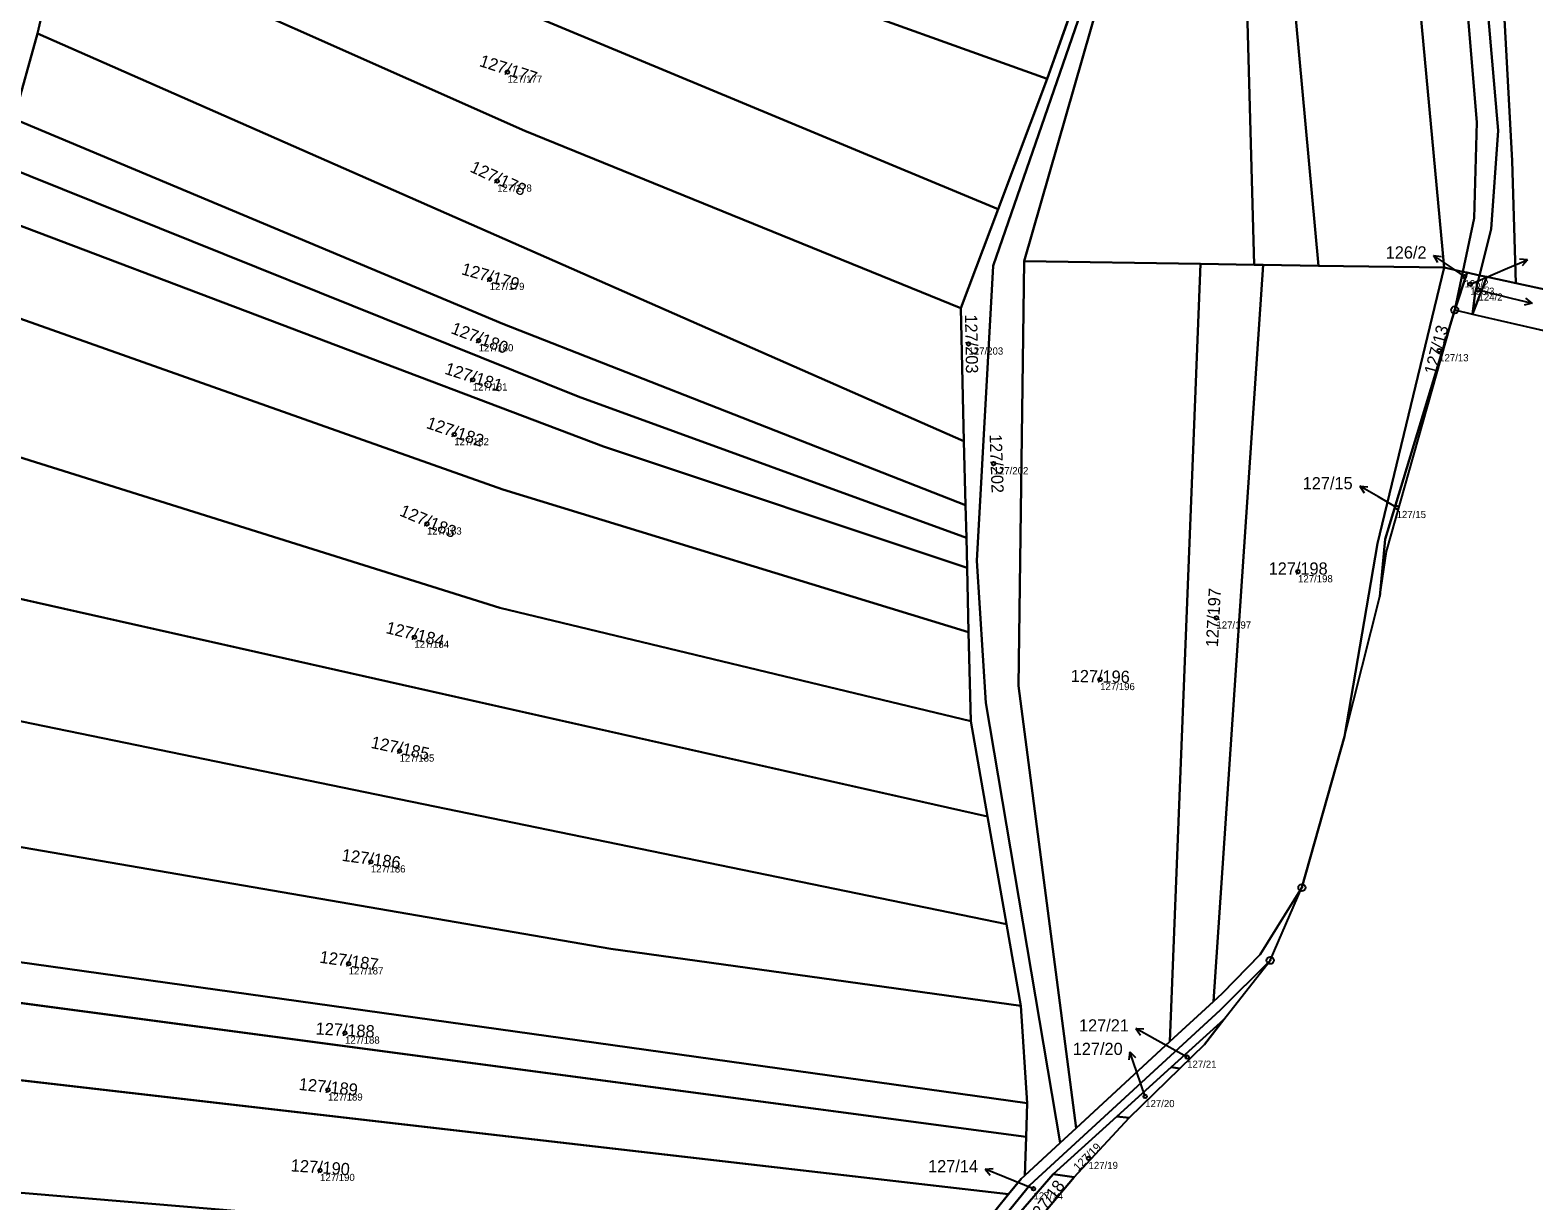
# Model space of a CAD drawing. Extents: x -603967 to -594699, y -1179315 to -1165625.
# Drawn here: x -597543.8 to -597334.3, y -1173385.4 to -1173222.3 of the extents above; entities that cross this region are included whole.
import ezdxf

# ---------------------------------------------------------------- set-up
doc = ezdxf.new("R2010")
doc.units = 0
for name, color, linetype in [('Definiční body', 7, 'Continuous'), ('Hranice parcel', 7, 'Continuous'), ('Parcelní čísla', 7, 'Continuous'), ('Polygon ku', 7, 'Continuous'), ('Polygon parcely', 7, 'Continuous'), ('Pop  PČ popisy', 7, 'Continuous'), ('Značky bodu BP', 7, 'Continuous')]:
    doc.layers.add(name, color=color, linetype=linetype)

msp = doc.modelspace()

# ---------------------------------------------------------------- linework, layer by layer
at = {"layer": 'Definiční body'}
for centre in [(-597477.29, -1173228.12994), (-597478.73, -1173243.29994), (-597343.99, -1173256.61994), (-597479.76, -1173256.98994), (-597343.17, -1173257.65994), (-597342.03, -1173258.45994), (-597481.3, -1173265.53994), (-597413.07, -1173265.98994), (-597347.51, -1173266.91994), (-597482.12, -1173270.98994), (-597484.7, -1173278.60994), (-597409.57, -1173282.65994), (-597353.44, -1173288.75994), (-597488.5, -1173291.05994), (-597367.17, -1173297.69994), (-597378.54, -1173304.14994), (-597490.25, -1173306.82994), (-597394.74, -1173312.71994), (-597492.31, -1173322.67994), (-597496.32, -1173338.11994), (-597499.41, -1173352.31994), (-597499.92, -1173361.95994), (-597382.62, -1173365.31994), (-597502.29, -1173369.88994), (-597388.46, -1173370.79994), (-597396.35, -1173379.41994), (-597503.39, -1173381.08994), (-597404.02, -1173383.65994)]:
    msp.add_circle(centre, 0.25, dxfattribs=at)
at = {"layer": 'Hranice parcel'}
for p, q in [((-597539.27, -1173207.67), (-597542.73, -1173222.74)), ((-597402.11, -1173229.07), (-597397.53, -1173216.17)), ((-597542.73, -1173222.74), (-597546.06, -1173234.64)), ((-597542.73, -1173222.74), (-597413.7, -1173279.52)), ((-597408.96, -1173247.24), (-597402.11, -1173229.07)), ((-597414.15, -1173260.99), (-597408.96, -1173247.24)), ((-597380.77, -1173254.84), (-597405.32, -1173254.45)), ((-597385.02, -1173363.15), (-597380.77, -1173254.84)), ((-597373.26, -1173254.96), (-597380.77, -1173254.84)), ((-597378.97, -1173357.58), (-597372.02, -1173254.98)), ((-597372.02, -1173254.98), (-597373.26, -1173254.96)), ((-597364.3, -1173255.1), (-597372.02, -1173254.98)), ((-597346.84, -1173255.37), (-597364.3, -1173255.1)), ((-597344.24, -1173255.93), (-597346.84, -1173255.37)), ((-597344.24, -1173255.93), (-597345.35, -1173261.25)), ((-597345.35, -1173261.25), (-597343.63, -1173256.06)), ((-597344.24, -1173255.93), (-597343.63, -1173256.06)), ((-597343.63, -1173256.06), (-597341.88, -1173256.44)), ((-597340.86, -1173256.64), (-597341.88, -1173256.44)), ((-597342.88, -1173261.85), (-597340.86, -1173256.64)), ((-597336.82, -1173257.52), (-597340.86, -1173256.64)), ((-597413.7, -1173279.52), (-597414.15, -1173260.99)), ((-597354.85, -1173294.92), (-597345.35, -1173261.25)), ((-597345.35, -1173261.25), (-597342.88, -1173261.85)), ((-597342.88, -1173261.85), (-597207.7, -1173292.76)), ((-597413.48, -1173288.43), (-597413.7, -1173279.52)), ((-597413.37, -1173293.01), (-597413.48, -1173288.43)), ((-597413.27, -1173297.18), (-597413.37, -1173293.01)), ((-597355.78, -1173301.19), (-597354.85, -1173294.92)), ((-597567.88, -1173296.4), (-597410.41, -1173331.83)), ((-597413.05, -1173306.13), (-597413.27, -1173297.18)), ((-597360.7, -1173320.68), (-597355.78, -1173301.19)), ((-597412.75, -1173318.55), (-597413.05, -1173306.13)), ((-597573.63, -1173312.68), (-597407.77, -1173346.82)), ((-597410.41, -1173331.83), (-597412.75, -1173318.55)), ((-597360.7, -1173320.68), (-597366.63, -1173341.72)), ((-597407.77, -1173346.82), (-597410.41, -1173331.83)), ((-597371.05, -1173351.85), (-597366.63, -1173341.72)), ((-597584.72, -1173346.58), (-597404.9, -1173371.72)), ((-597405.77, -1173358.17), (-597407.77, -1173346.82)), ((-597588.05, -1173352.06), (-597405.06, -1173376.43)), ((-597377.5, -1173360.1), (-597371.05, -1173351.85)), ((-597404.9, -1173371.72), (-597405.77, -1173358.17)), ((-597378.97, -1173357.58), (-597385.02, -1173363.15)), ((-597384.85, -1173366.74), (-597377.5, -1173360.1)), ((-597594.6, -1173362.84), (-597407.48, -1173384.43)), ((-597385.02, -1173363.15), (-597398.08, -1173375.21)), ((-597392.4, -1173373.59), (-597384.85, -1173366.74)), ((-597390.69, -1173373.8), (-597383.65, -1173366.92)), ((-597383.65, -1173366.92), (-597384.85, -1173366.74)), ((-597405.06, -1173376.43), (-597404.9, -1173371.72)), ((-597401.29, -1173381.61), (-597392.4, -1173373.59)), ((-597390.69, -1173373.8), (-597392.4, -1173373.59)), ((-597398.08, -1173375.21), (-597400.29, -1173377.25)), ((-597398.37, -1173382.03), (-597390.69, -1173373.8)), ((-597405.24, -1173381.82), (-597405.06, -1173376.43)), ((-597400.29, -1173377.25), (-597405.24, -1173381.82)), ((-597608.97, -1173378.82), (-597416.1, -1173395.08)), ((-597407.87, -1173389.24), (-597401.29, -1173381.61)), ((-597398.37, -1173382.03), (-597404.78, -1173389.65)), ((-597401.29, -1173381.61), (-597398.37, -1173382.03)), ((-597407.48, -1173384.43), (-597416.1, -1173395.08))]:
    msp.add_line(p, q, dxfattribs=at)
for points in [[(-597341.88, -1173256.44), (-597340.26, -1173250.03), (-597339.32, -1173236.26), (-597344.17, -1173179.9), (-597353.54, -1173132.63), (-597361.17, -1173091.31), (-597366.08, -1173066.31), (-597374.64, -1173050.36), (-597380.37, -1173039.62), (-597387.47, -1173019.8), (-597399.32, -1172964.53), (-597404.92, -1172923.92), (-597423.04, -1172835.13), (-597437.05, -1172782.74)], [(-597385.23, -1173035.74), (-597369.64, -1173064.26), (-597366.45, -1173075.97), (-597356.05, -1173133.92), (-597346.95, -1173178.93), (-597342.27, -1173235.11), (-597342.62, -1173248.49), (-597344.24, -1173255.93)], [(-597373.26, -1173254.96), (-597374.47, -1173211.02), (-597373.85, -1173166.41), (-597375.69, -1173097.31), (-597378.77, -1173058.37)], [(-597364.3, -1173255.1), (-597367.48, -1173220.7), (-597367.67, -1173176.36), (-597372.2, -1173099.16), (-597376.39, -1173065.79)], [(-597346.84, -1173255.37), (-597353.46, -1173183.74), (-597366.22, -1173097.48), (-597376.39, -1173065.79)], [(-597380.95, -1173103.54), (-597382.69, -1173103.69), (-597389.48, -1173147.51), (-597392.36, -1173174.23), (-597394.01, -1173209.84), (-597409.64, -1173255.1), (-597411.9, -1173296.2), (-597410.66, -1173315.96), (-597400.29, -1173377.25)], [(-597380.95, -1173103.54), (-597388.45, -1173157.59), (-597392.56, -1173210), (-597405.32, -1173254.45)], [(-597531.27, -1173180.19), (-597472.58, -1173203.79), (-597402.11, -1173229.07)], [(-597340.37, -1173184.71), (-597337.35, -1173240.49), (-597336.82, -1173257.52)], [(-597535.59, -1173193.78), (-597474.9, -1173219.8), (-597408.96, -1173247.24)], [(-597539.27, -1173207.67), (-597474.86, -1173236.29), (-597414.15, -1173260.99)], [(-597546.06, -1173234.64), (-597477.92, -1173263.21), (-597413.48, -1173288.43)], [(-597548.33, -1173240.82), (-597467.43, -1173273.3), (-597413.37, -1173293.01)], [(-597550.79, -1173247.41), (-597463.93, -1173280.29), (-597413.27, -1173297.18)], [(-597405.32, -1173254.45), (-597406.11, -1173313.63), (-597398.08, -1173375.21)], [(-597346.84, -1173255.37), (-597356.1, -1173293.81), (-597360.7, -1173320.68)], [(-597341.88, -1173256.44), (-597342.48, -1173258.83), (-597342.88, -1173261.85)], [(-597203.06, -1173285.97), (-597235.54, -1173279.29), (-597273.37, -1173276.16), (-597302.53, -1173264.95), (-597336.82, -1173257.52)], [(-597555.73, -1173258.73), (-597477.92, -1173286.26), (-597413.05, -1173306.13)], [(-597355.78, -1173301.19), (-597355.05, -1173293.18), (-597345.35, -1173261.25)], [(-597559.64, -1173277.25), (-597478.33, -1173302.73), (-597412.75, -1173318.55)], [(-597579.78, -1173330.11), (-597462.89, -1173350.25), (-597405.77, -1173358.17)], [(-597366.63, -1173341.72), (-597372.44, -1173351.02), (-597377.75, -1173356.45), (-597378.97, -1173357.58)], [(-597422.2, -1173415.24), (-597419.31, -1173405.08), (-597414.89, -1173395.86), (-597404.55, -1173383.14), (-597378.04, -1173358.78), (-597371.05, -1173351.85)], [(-597377.5, -1173360.1), (-597380.18, -1173363.56), (-597383.65, -1173366.92)], [(-597405.24, -1173381.82), (-597405.74, -1173382.28), (-597407.48, -1173384.43)]]:
    msp.add_lwpolyline(points, dxfattribs=at)
at = {"layer": 'Polygon ku'}
msp.add_lwpolyline([(-597404.78, -1173389.65), (-597398.37, -1173382.03), (-597390.69, -1173373.8), (-597383.65, -1173366.92), (-597380.18, -1173363.56), (-597377.5, -1173360.1), (-597371.05, -1173351.85), (-597366.63, -1173341.72), (-597360.7, -1173320.68), (-597355.78, -1173301.19), (-597354.85, -1173294.92), (-597345.35, -1173261.25), (-597342.88, -1173261.85), (-597207.7, -1173292.76)], dxfattribs=at)
at = {"layer": 'Polygon parcely'}
for points in [[(-597401.86, -1172966.79), (-597391.47, -1173016.9), (-597386.2, -1173032.57), (-597385.23, -1173035.74), (-597369.64, -1173064.26), (-597366.45, -1173075.97), (-597356.05, -1173133.92), (-597346.95, -1173178.93), (-597342.27, -1173235.11), (-597342.62, -1173248.49), (-597344.24, -1173255.93), (-597343.63, -1173256.06), (-597341.88, -1173256.44), (-597340.26, -1173250.03), (-597339.32, -1173236.26), (-597344.17, -1173179.9), (-597353.54, -1173132.63), (-597361.17, -1173091.31), (-597366.08, -1173066.31), (-597374.64, -1173050.36), (-597380.37, -1173039.62), (-597387.47, -1173019.8), (-597399.32, -1172964.53)], [(-597399.32, -1172964.53), (-597387.47, -1173019.8), (-597380.37, -1173039.62), (-597374.64, -1173050.36), (-597366.08, -1173066.31), (-597361.17, -1173091.31), (-597353.54, -1173132.63), (-597344.17, -1173179.9), (-597339.32, -1173236.26), (-597340.26, -1173250.03), (-597341.88, -1173256.44), (-597340.86, -1173256.64), (-597336.82, -1173257.52), (-597337.35, -1173240.49), (-597340.37, -1173184.71), (-597357.02, -1173091.48), (-597366.96, -1173054.01), (-597384.66, -1173008.07)], [(-597629.76, -1173398.17), (-597608.97, -1173378.82), (-597594.6, -1173362.84), (-597588.05, -1173352.06), (-597584.72, -1173346.58), (-597579.78, -1173330.11), (-597573.63, -1173312.68), (-597567.88, -1173296.4), (-597559.64, -1173277.25), (-597555.73, -1173258.73), (-597550.79, -1173247.41), (-597548.33, -1173240.82), (-597546.06, -1173234.64), (-597542.73, -1173222.74), (-597539.27, -1173207.67)], [(-597397.53, -1173216.17), (-597402.11, -1173229.07), (-597408.96, -1173247.24), (-597414.15, -1173260.99), (-597413.7, -1173279.52), (-597413.48, -1173288.43), (-597413.37, -1173293.01), (-597413.27, -1173297.18), (-597413.05, -1173306.13), (-597412.75, -1173318.55), (-597410.41, -1173331.83), (-597407.77, -1173346.82), (-597405.77, -1173358.17), (-597404.9, -1173371.72), (-597405.06, -1173376.43), (-597405.24, -1173381.82), (-597400.29, -1173377.25), (-597410.66, -1173315.96), (-597411.9, -1173296.2), (-597409.64, -1173255.1), (-597394.01, -1173209.84)], [(-597414.89, -1173395.86), (-597404.55, -1173383.14), (-597378.04, -1173358.78), (-597371.05, -1173351.85), (-597366.63, -1173341.72), (-597372.44, -1173351.02), (-597377.75, -1173356.45), (-597378.97, -1173357.58), (-597385.02, -1173363.15), (-597398.08, -1173375.21), (-597400.29, -1173377.25), (-597405.24, -1173381.82), (-597405.74, -1173382.28), (-597407.48, -1173384.43), (-597416.1, -1173395.08)]]:
    msp.add_lwpolyline(points, dxfattribs=at)
for points in [[(-597388.35, -1173035.34), (-597378.77, -1173058.37), (-597376.39, -1173065.79), (-597366.22, -1173097.48), (-597353.46, -1173183.74), (-597346.84, -1173255.37), (-597344.24, -1173255.93), (-597342.62, -1173248.49), (-597342.27, -1173235.11), (-597346.95, -1173178.93), (-597356.05, -1173133.92), (-597366.45, -1173075.97), (-597369.64, -1173064.26), (-597385.23, -1173035.74)], [(-597375.69, -1173097.31), (-597378.77, -1173058.37), (-597382.07, -1173058.99), (-597380.42, -1173099.75), (-597380.95, -1173103.54), (-597388.45, -1173157.59), (-597392.56, -1173210), (-597405.32, -1173254.45), (-597380.77, -1173254.84), (-597373.26, -1173254.96), (-597374.47, -1173211.02), (-597373.85, -1173166.41)], [(-597367.48, -1173220.7), (-597367.67, -1173176.36), (-597372.2, -1173099.16), (-597376.39, -1173065.79), (-597378.77, -1173058.37), (-597375.69, -1173097.31), (-597373.85, -1173166.41), (-597374.47, -1173211.02), (-597373.26, -1173254.96), (-597372.02, -1173254.98), (-597364.3, -1173255.1)], [(-597366.22, -1173097.48), (-597376.39, -1173065.79), (-597372.2, -1173099.16), (-597367.67, -1173176.36), (-597367.48, -1173220.7), (-597364.3, -1173255.1), (-597346.84, -1173255.37), (-597353.46, -1173183.74)], [(-597394.01, -1173209.84), (-597409.64, -1173255.1), (-597411.9, -1173296.2), (-597410.66, -1173315.96), (-597400.29, -1173377.25), (-597398.08, -1173375.21), (-597406.11, -1173313.63), (-597405.32, -1173254.45), (-597392.56, -1173210), (-597388.45, -1173157.59), (-597380.95, -1173103.54), (-597382.69, -1173103.69), (-597389.48, -1173147.51), (-597392.36, -1173174.23)], [(-597402.11, -1173229.07), (-597397.53, -1173216.17), (-597460.65, -1173193.08), (-597525.71, -1173167.84), (-597531.27, -1173180.19), (-597472.58, -1173203.79)], [(-597167.37, -1173173.96), (-597172.05, -1173173.96), (-597173.32, -1173182.18), (-597260.83, -1173182.27), (-597260.84, -1173174.27), (-597271.15, -1173169.07), (-597287.52, -1173170.77), (-597299.69, -1173173.18), (-597340.37, -1173184.71), (-597337.35, -1173240.49), (-597336.82, -1173257.52), (-597302.53, -1173264.95), (-597273.37, -1173276.16), (-597235.54, -1173279.29), (-597203.06, -1173285.97)], [(-597408.96, -1173247.24), (-597402.11, -1173229.07), (-597472.58, -1173203.79), (-597531.27, -1173180.19), (-597535.59, -1173193.78), (-597474.9, -1173219.8)], [(-597539.27, -1173207.67), (-597474.86, -1173236.29), (-597414.15, -1173260.99), (-597408.96, -1173247.24), (-597474.9, -1173219.8), (-597535.59, -1173193.78)], [(-597542.73, -1173222.74), (-597413.7, -1173279.52), (-597414.15, -1173260.99), (-597474.86, -1173236.29), (-597539.27, -1173207.67)], [(-597413.48, -1173288.43), (-597413.7, -1173279.52), (-597542.73, -1173222.74), (-597546.06, -1173234.64), (-597477.92, -1173263.21)], [(-597548.33, -1173240.82), (-597467.43, -1173273.3), (-597413.37, -1173293.01), (-597413.48, -1173288.43), (-597477.92, -1173263.21), (-597546.06, -1173234.64)], [(-597413.27, -1173297.18), (-597413.37, -1173293.01), (-597467.43, -1173273.3), (-597548.33, -1173240.82), (-597550.79, -1173247.41), (-597463.93, -1173280.29)], [(-597477.92, -1173286.26), (-597413.05, -1173306.13), (-597413.27, -1173297.18), (-597463.93, -1173280.29), (-597550.79, -1173247.41), (-597555.73, -1173258.73)], [(-597385.02, -1173363.15), (-597380.77, -1173254.84), (-597405.32, -1173254.45), (-597406.11, -1173313.63), (-597398.08, -1173375.21)], [(-597380.77, -1173254.84), (-597385.02, -1173363.15), (-597378.97, -1173357.58), (-597372.02, -1173254.98), (-597373.26, -1173254.96)], [(-597372.02, -1173254.98), (-597378.97, -1173357.58), (-597377.75, -1173356.45), (-597372.44, -1173351.02), (-597366.63, -1173341.72), (-597360.7, -1173320.68), (-597356.1, -1173293.81), (-597346.84, -1173255.37), (-597364.3, -1173255.1)], [(-597355.05, -1173293.18), (-597345.35, -1173261.25), (-597344.24, -1173255.93), (-597346.84, -1173255.37), (-597356.1, -1173293.81), (-597360.7, -1173320.68), (-597355.78, -1173301.19)], [(-597343.63, -1173256.06), (-597344.24, -1173255.93), (-597345.35, -1173261.25)], [(-597345.35, -1173261.25), (-597342.88, -1173261.85), (-597342.48, -1173258.83), (-597341.88, -1173256.44), (-597343.63, -1173256.06)], [(-597341.88, -1173256.44), (-597342.48, -1173258.83), (-597342.88, -1173261.85), (-597340.86, -1173256.64)], [(-597203.06, -1173285.97), (-597235.54, -1173279.29), (-597273.37, -1173276.16), (-597302.53, -1173264.95), (-597336.82, -1173257.52), (-597340.86, -1173256.64), (-597342.88, -1173261.85), (-597207.7, -1173292.76), (-597205.44, -1173293.26)], [(-597559.64, -1173277.25), (-597478.33, -1173302.73), (-597412.75, -1173318.55), (-597413.05, -1173306.13), (-597477.92, -1173286.26), (-597555.73, -1173258.73)], [(-597345.35, -1173261.25), (-597355.05, -1173293.18), (-597355.78, -1173301.19), (-597354.85, -1173294.92)], [(-597567.88, -1173296.4), (-597410.41, -1173331.83), (-597412.75, -1173318.55), (-597478.33, -1173302.73), (-597559.64, -1173277.25)], [(-597407.77, -1173346.82), (-597410.41, -1173331.83), (-597567.88, -1173296.4), (-597573.63, -1173312.68)], [(-597405.77, -1173358.17), (-597407.77, -1173346.82), (-597573.63, -1173312.68), (-597579.78, -1173330.11), (-597462.89, -1173350.25)], [(-597404.9, -1173371.72), (-597405.77, -1173358.17), (-597462.89, -1173350.25), (-597579.78, -1173330.11), (-597584.72, -1173346.58)], [(-597588.05, -1173352.06), (-597405.06, -1173376.43), (-597404.9, -1173371.72), (-597584.72, -1173346.58)], [(-597407.48, -1173384.43), (-597405.74, -1173382.28), (-597405.24, -1173381.82), (-597405.06, -1173376.43), (-597588.05, -1173352.06), (-597594.6, -1173362.84)], [(-597377.5, -1173360.1), (-597371.05, -1173351.85), (-597378.04, -1173358.78), (-597404.55, -1173383.14), (-597414.89, -1173395.86), (-597419.31, -1173405.08), (-597422.2, -1173415.24), (-597417.05, -1173404.27), (-597413.44, -1173396.34), (-597407.87, -1173389.24), (-597401.29, -1173381.61), (-597392.4, -1173373.59), (-597384.85, -1173366.74)], [(-597377.5, -1173360.1), (-597384.85, -1173366.74), (-597383.65, -1173366.92), (-597380.18, -1173363.56)], [(-597416.1, -1173395.08), (-597407.48, -1173384.43), (-597594.6, -1173362.84), (-597608.97, -1173378.82)], [(-597383.65, -1173366.92), (-597384.85, -1173366.74), (-597392.4, -1173373.59), (-597390.69, -1173373.8)], [(-597401.29, -1173381.61), (-597398.37, -1173382.03), (-597390.69, -1173373.8), (-597392.4, -1173373.59)], [(-597421, -1173405.44), (-597416.1, -1173395.08), (-597608.97, -1173378.82), (-597629.76, -1173398.17)], [(-597401.29, -1173381.61), (-597407.87, -1173389.24), (-597404.78, -1173389.65), (-597398.37, -1173382.03)]]:
    msp.add_lwpolyline(points, close=True, dxfattribs=at)
at = {"layer": 'Pop  PČ popisy'}
for p, q in [((-597345.82, -1173255.37), (-597348.308, -1173253.692)), ((-597348.308, -1173253.692), (-597347.198, -1173253.837)), ((-597348.308, -1173253.692), (-597347.758, -1173254.667)), ((-597337.99, -1173255.43), (-597335.228, -1173254.257)), ((-597335.228, -1173254.257), (-597336.345, -1173254.188)), ((-597335.228, -1173254.257), (-597335.954, -1173255.11)), ((-597343.99, -1173256.62), (-597345.82, -1173255.37)), ((-597343.17, -1173257.66), (-597337.99, -1173255.43)), ((-597342.03, -1173258.46), (-597337.49, -1173259.61)), ((-597337.49, -1173259.61), (-597334.578, -1173260.336)), ((-597334.578, -1173260.336), (-597335.671, -1173260.58)), ((-597334.578, -1173260.336), (-597335.429, -1173259.608)), ((-597355.98, -1173287.31), (-597358.579, -1173285.81)), ((-597358.579, -1173285.81), (-597357.461, -1173285.877)), ((-597358.579, -1173285.81), (-597357.962, -1173286.744)), ((-597353.44, -1173288.76), (-597355.98, -1173287.31)), ((-597387.13, -1173362.8), (-597389.755, -1173361.345)), ((-597389.755, -1173361.345), (-597388.636, -1173361.393)), ((-597389.755, -1173361.345), (-597389.122, -1173362.269)), ((-597382.62, -1173365.32), (-597387.13, -1173362.8)), ((-597390.607, -1173364.593), (-597390.754, -1173365.702)), ((-597389.63, -1173367.43), (-597390.607, -1173364.593)), ((-597390.607, -1173364.593), (-597389.808, -1173365.376)), ((-597388.46, -1173370.8), (-597389.63, -1173367.43)), ((-597410.772, -1173380.936), (-597409.656, -1173380.847)), ((-597407.99, -1173382.06), (-597410.772, -1173380.936)), ((-597410.772, -1173380.936), (-597410.032, -1173381.775)), ((-597404.02, -1173383.66), (-597407.99, -1173382.06))]:
    msp.add_line(p, q, dxfattribs=at)
at = {"layer": 'Značky bodu BP'}
for centre, radius in [((-597345.35, -1173261.24988), 0.5), ((-597345.35, -1173261.24988), 0.0303), ((-597366.63, -1173341.71988), 0.5), ((-597366.63, -1173341.71988), 0.0303), ((-597371.05, -1173351.84988), 0.5), ((-597371.05, -1173351.84988), 0.0303)]:
    msp.add_circle(centre, radius, dxfattribs=at)

# ---------------------------------------------------------------- texts
at = {"layer": 'Definiční body'}
for s, p in [('127/177', (-597477.29, -1173229.619)), ('127/178', (-597478.73, -1173244.789)), ('127/179', (-597479.76, -1173258.479)), ('126/2', (-597343.99, -1173258.109)), ('126/3', (-597343.17, -1173259.149)), ('124/2', (-597342.03, -1173259.949)), ('127/180', (-597481.3, -1173267.029)), ('127/203', (-597413.07, -1173267.479)), ('127/13', (-597347.51, -1173268.409)), ('127/181', (-597482.12, -1173272.479)), ('127/182', (-597484.7, -1173280.099)), ('127/202', (-597409.57, -1173284.149)), ('127/15', (-597353.44, -1173290.249)), ('127/183', (-597488.5, -1173292.549)), ('127/198', (-597367.17, -1173299.189)), ('127/197', (-597378.54, -1173305.639)), ('127/184', (-597490.25, -1173308.319)), ('127/196', (-597394.74, -1173314.209)), ('127/185', (-597492.31, -1173324.169)), ('127/186', (-597496.32, -1173339.609)), ('127/187', (-597499.41, -1173353.809)), ('127/188', (-597499.92, -1173363.449)), ('127/21', (-597382.62, -1173366.809)), ('127/189', (-597502.29, -1173371.379)), ('127/20', (-597388.46, -1173372.289)), ('127/19', (-597396.35, -1173380.909)), ('127/190', (-597503.39, -1173382.579)), ('127/14', (-597404.02, -1173385.149))]:
    msp.add_text(s, height=0.999996, dxfattribs=at).set_placement(p)
at = {"layer": 'Parcelní čísla'}
for s, height, rotation, p in [('127/177', 1.699998, 342, (-597481.317, -1173227.268)), ('127/178', 1.699998, 335, (-597482.622, -1173241.953)), ('127/179', 1.699998, 344, (-597483.815, -1173256.269)), ('127/203', 1.699998, 271, (-597413.566, -1173261.901)), ('127/180', 1.699998, 339, (-597485.276, -1173264.468)), ('127/13', 1.699998, 75, (-597347.996, -1173270.378)), ('127/181', 1.699998, 342, (-597486.147, -1173270.128)), ('127/182', 1.699998, 340.9999972, (-597488.711, -1173277.678)), ('127/202', 1.699998, 272, (-597410.137, -1173278.58)), ('127/183', 1.699998, 337, (-597492.437, -1173289.85)), ('127/197', 1.699998, 87, (-597378.329, -1173308.263)), ('127/184', 1.699998, 346, (-597494.327, -1173306.251)), ('127/196', 1.699998, 359, (-597398.843, -1173313.073)), ('127/185', 1.699998, 348, (-597496.405, -1173322.243)), ('127/186', 1.699998, 351.9999972, (-597500.435, -1173337.97)), ('127/187', 1.699998, 351.9999972, (-597503.525, -1173352.17)), ('127/188', 1.699998, 357, (-597504.033, -1173362.17)), ('127/189', 1.699998, 354, (-597506.408, -1173369.884)), ('127/19', 1.14, 45, (-597397.792, -1173381.265)), ('127/190', 1.699998, 356, (-597507.506, -1173381.228)), ('127/18', 1.699998, 53, (-597403.736, -1173388.814))]:
    msp.add_text(s, height=height, rotation=rotation, dxfattribs=at).set_placement(p)
for s, p in [('126/2', (-597354.962, -1173254.095)), ('127/15', (-597366.522, -1173286.245)), ('127/198', (-597371.266, -1173298.125)), ('127/21', (-597397.682, -1173361.755)), ('127/20', (-597398.552, -1173365.025)), ('127/14', (-597418.702, -1173381.365))]:
    msp.add_text(s, height=1.699998, dxfattribs=at).set_placement(p)

doc.saveas('drawing.dxf')
